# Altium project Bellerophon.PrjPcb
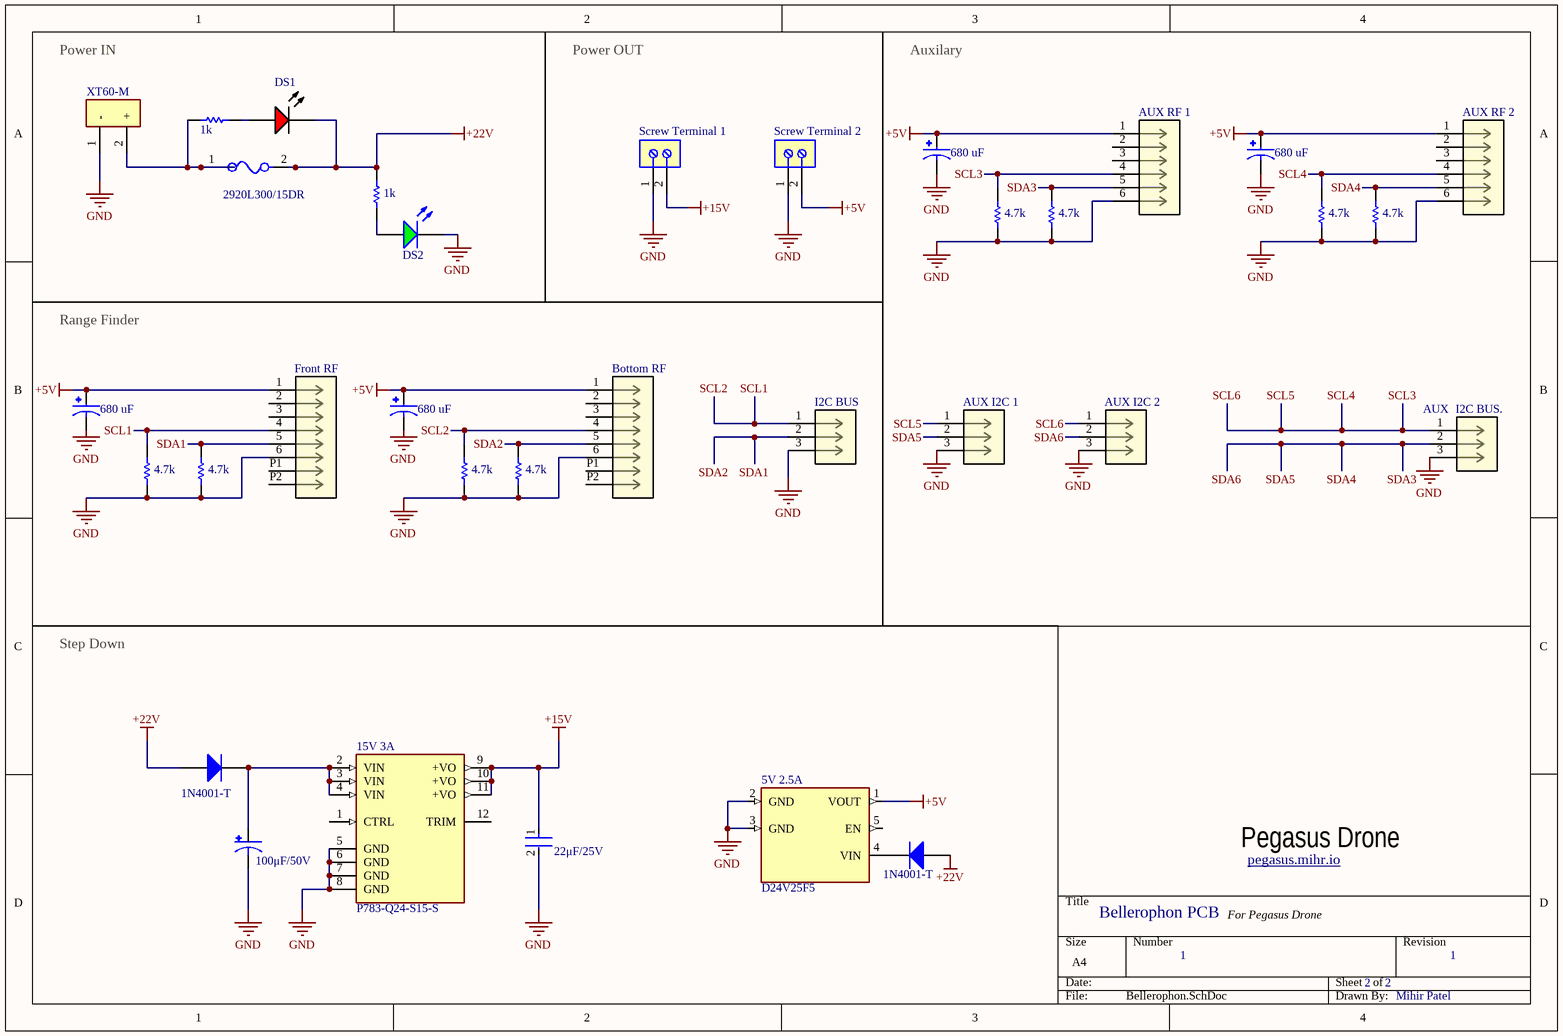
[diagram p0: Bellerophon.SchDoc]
1 sheet, 34 parts. Net scope: global (net labels, ports and power ports of the same name join across sheets).
Board file: Bellerophon.PcbDoc

## Sheet Bellerophon.SchDoc
size A4; SheetNumber: 3; SheetTotal: 3

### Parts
5V_2.5A  D24V25F5  [XDCR_12V_2.2A_STEP-DOWN_D24V22F12]
15V_3A  P783-Q24-S15-S  [CONV_P783-Q24-S15-S]
+5VDC  Screw Terminal 2  [PHOE-1725656-2]
+15VDC  Screw Terminal 1  [PHOE-1725656-2]
AUX_I2C_1  1053131303  [CON_1053131303]  (value not drawn)
AUX_I2C_2  1053131303  [CON_1053131303]  (value not drawn)
AUX_RF_1  1053131306  [CON_1053131306]  (value not drawn)
AUX_RF_2  1053131306  [CON_1053131306]  (value not drawn)
Bottom_RF  1053111306  [CON_1053111306_MOL]  (value not drawn)
C1  100μF/50V  [CAPAE830X1020N]
C2  22μF/25V  [FP-1210-L_3_3_0_4-W_2_5_0-MFG]
C3  680 uF  [CAP_EEEFN0J681V]
C4  680 uF  [CAP_EEEFN0J681V]
C5  680 uF  [CAP_EEEFN0J681V]
C6  680 uF  [CAP_EEEFN0J681V]
D1  1N4001-T  [DIOD-DO-41-P-2_V]
D2  1N4001-T  [DIOD-DO-41-P-2_V]
DS1  SML-LX1206IC-TR  [LUMX-SML-LX1206IC_V]  (value not drawn)
DS2  SML-LX1206GC-TR  [LUMX-SML-LX1206GC-TR_V]  (value not drawn)
F1  2920L300/15DR  [FP-2920L-MFG]
Front_RF  1053111306  [CON_1053111306_MOL]  (value not drawn)
I2C_BUS  1053091303  [CON_1053091303]  (value not drawn)
I2C_BUS.  1053131303  [CON_1053131303]  (value not drawn)
R1  1k  [RESC3225X70X50NL20T20]
R2  1k  [RESC3225X70X50NL20T20]
R3  4.7k  [RESC3225X70X50NL20T20]
R4  4.7k  [RESC3225X70X50NL20T20]
R5  4.7k  [RESC3225X70X50NL20T20]
R6  4.7k  [RESC3225X70X50NL20T20]
R7  4.7k  [RESC3225X70X50NL20T20]
R8  4.7k  [RESC3225X70X50NL20T20]
R9  4.7k  [RESC3225X70X50NL20T20]
R10  4.7k  [RESC3225X70X50NL20T20]
VIN  XT60-M  [AMASS_XT60-M]

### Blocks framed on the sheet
Power IN: DS1 DS2 F1 R1 R2 VIN
Power OUT: +5VDC +15VDC
Auxilary: AUX_I2C_1 AUX_I2C_2 AUX_RF_1 AUX_RF_2 C5 C6 I2C_BUS. R7-R10
Range Finder: Bottom_RF C3 C4 Front_RF I2C_BUS R3-R6
Step Down: 5V_2.5A 15V_3A C1 C2 D1 D2

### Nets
+5V: 5V_2.5A.1(VOUT) +5VDC.2 AUX_RF_1.1 AUX_RF_2.1 Bottom_RF.1 C3.1 C4.1 C5.1 C6.1 Front_RF.1
+15V: 15V_3A.9(+VO) 15V_3A.10(+VO) 15V_3A.11(+VO) +15VDC.2 C2.1
+22V: D1.1(A) D2.1(A) DS1.2(K) F1.2 R2.1
GND: 5V_2.5A.2(GND) 5V_2.5A.3(GND) 15V_3A.5(GND) 15V_3A.6(GND) 15V_3A.7(GND) 15V_3A.8(GND) +5VDC.1 +15VDC.1 AUX_I2C_1.3 AUX_I2C_2.3 AUX_RF_1.6 AUX_RF_2.6 Bottom_RF.6 C1.2(NEG) C2.2 C5.2 C6.2 DS2.2(K) Front_RF.6 I2C_BUS.3 I2C_BUS..3 R3.2 R4.2 R5.2 R6.2 R7.2 R8.2 R9.2 R10.2 VIN.1(-)
SCL1: Bottom_RF.4 Front_RF.4 I2C_BUS.1 R4.1 R6.1  [also labelled SCL2]
SCL3: AUX_I2C_1.1 AUX_I2C_2.1 AUX_RF_1.4 AUX_RF_2.4 I2C_BUS..1 R8.1 R10.1  [also labelled SCL4, SCL5, SCL6]
SDA1: Bottom_RF.5 Front_RF.5 I2C_BUS.2 R3.1 R5.1  [also labelled SDA2]
SDA3: AUX_I2C_1.2 AUX_I2C_2.2 AUX_RF_1.5 AUX_RF_2.5 I2C_BUS..2 R7.1 R9.1  [also labelled SDA4, SDA5, SDA6]
Net5V_2.5A_4: 5V_2.5A.4(VIN) D2.2(K)
Net15V_3A_2: 15V_3A.2(VIN) 15V_3A.3(VIN) 15V_3A.4(VIN) C1.1(POS) D1.2(K)
NetDS1_1: DS1.1(A) R1.2
NetDS2_1: DS2.1(A) R2.2
NetF1_1: F1.1 R1.1 VIN.2(+)

Not connected (* = marked no-connect by the designer): 5V_2.5A 5(EN) 6(GND); 15V_3A 1(CTRL) 12(TRIM); AUX_RF_1 2 3; AUX_RF_2 2 3; Bottom_RF 2 3 P1 P2; C3 2; C4 2; Front_RF 2 3 P1 P2

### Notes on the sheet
- (near I2C_BUS.) AUX
- Pegasus Drone
- Bellerophon PCB
- For Pegasus Drone
- pegasus.mihr.io <http://pegasus.mihr.io>
- 1
- 2
- Mihir Patel
- Labels drawn without touching a wire or pin: GND

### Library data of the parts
5V_2.5A = 12V_2.2A_STEP-DOWN_D24V22F12: Converter: step down; Uin: 12.7Ã·36V; Uout: 12V; 2200mA; 90Ã·95%; MP: 12V 2.2A STEP-DOWN D24V22F12; MF: Pololu
+5VDC +15VDC = CMP-2000-05299-1: Male Header, Pitch 2.54 mm, 1 x 2 Position, Height 9 mm, Tail Length 3.5 mm; Manufacturer part No.: 1725656; Manufacturer: Phoenix Contact; Number of contacts: 2; Content: 250pc(s); Pitch: 2.54mm; Industrial packaging: Yes
AUX_I2C_1 AUX_I2C_2 I2C_BUS. = 1053131303: No Description Available; Mfr_Name: Molex Connector Corporation
AUX_RF_1 AUX_RF_2 = 1053131306: No Description Available; Mfr_Name: Molex Connector Corporation
Bottom_RF Front_RF = 1053111306: No Description Available; Mfr_Name: Molex Connector Corporation
C1 = EDK107M050A9MAA: 100ÂµF 50V Aluminum Electrolytic Capacitors Radial, Can - SMD 2000 Hrs @ 85Â°C; MF: KEMET
C2 = CMP-2000-05483-2: General Purpose Ceramic Capacitor, 1210, 22uF, 10%, X5R, 15%, 16V
C3-C6 = EEEFN0J681V: CAP ALUM 680UF 20% 6.3V SMD; MF: Panasonic
D1 D2 = CMP-0639-00006-2: 1.0 A Rectifier, 15 pF, 50 V, -65 to 150 degC, 2-Pin DO-41 Plastic, RoHS, Tape and Reel; Manufacturer: Diodes Inc; VF (V): 1; CT (pF): 15; Max. IR (uA): 5; VRRM (V): 50; Max. IFSM (A): 30
DS1 = CMP-2000-07123-1: LED Red, 65 mW, -40 to 85 degC, 2-Pin SMD, RoHS, Tape and Reel; Manufacturer: Lumex; LED Material: GaAsP; Peak Wavelength: 635nm; Number of LEDs: 1; Viewing Angle: 160; Reverse Voltage: 5(Min)V; Lens Appearance: ColorlessNonDiffused; Intensity: 6mcd; Type: Uni-Color; Pin_Count: 2
DS2 = CMP-2000-07122-1: Green Led, Water Clear Lens, 10 mcd, 565 nm, 2.2 V, -40 to 85 degC, 2-Pin SMD, RoHS, Tape and Reel; Manufacturer: Lumex; Number of LEDs: 1; Type: Uni-Color; Viewing Angle: 160; Pin_Count: 2; Intensity: 10mcd; Reverse Voltage: 5(Min)V; COO: CN; LED Material: GaP; Peak Wavelength: 565nm; Lens Appearance: ColorlessNonDiffused
F1 = CMP-2000-05550-2: PTC RESET FUSE 15V 3A 2920; Manufacturer: Littelfuse; Current Rating: 40A; Trip Current: 5A; Trip Time: 20s; Resistance: 0.015-0.048Ω; Value: 0.015-0.048Ω
I2C_BUS = 1053091303: No Description Available; Mfr_Name: Molex Connector Corporation
R1-R10 = CMP-2005-03583-1: Part Number: ERJ-14YJ472U; Manufacturer: Panasonic
VIN = XT60-M: Plug; DC supply; XT60; male; PIN: 2; for cable; soldered; 30A; 500V; MF: AMASS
